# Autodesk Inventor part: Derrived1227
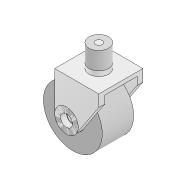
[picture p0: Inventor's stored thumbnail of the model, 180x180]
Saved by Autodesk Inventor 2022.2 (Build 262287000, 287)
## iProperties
Created: 2021-12
Part Number: Derrived1227
Material: 一般
Document SubType Name: Modeling
Designer: taeku
Density: 1 g/cm^3
Appearance: 既定
Author: taeku
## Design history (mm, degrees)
derived "Holder.ipt"
node "作業平面1"
feature "分割1"
  node "ソリッド1"
sketch "スケッチ1"
  geometry: C1 r 12 at (12, -40); C2 r 6 at (12, -40); A1 r 12 centre (12, -40) between (0, -40) and (21.996, -46.639) reference; 3 further points
  constraints: 2 centre point, 2 coincident
extrude "押し出し1" new body sketch "スケッチ1" distance "d2" = 6.5; taper "d3" = 0 deg
mirror "ミラー1"
sketch "スケッチ2"
  geometry: C1 r 6 at (0, 0); C2 r 30 at (0, 0); 1 further point
  constraints: 2 centre point, 2 coincident
  dimensions: "d4" = 60 diameter of C2
extrude "押し出し2" new body sketch "スケッチ2" stored distance "d5" = 32; taper "d6" = 0 deg
sketch "スケッチ3"
  geometry: C1 r 3.5 at (0, 0); C2 r 10 at (0, 0); 1 further point
  constraints: 2 centre point, 1 coincident
extrude "押し出し3" new body sketch "スケッチ3" stored distance "d7" = 33; taper "d8" = 0 deg
feature "ソリッド1::Holder.ipt" dims "d0" = 10
tag "TaggingFeature1"
node "保持2"
feature "次のパターン 保持2:1"
node "保持3"
node "障害物1"
node "障害物2"
node "保持1"
node "元の形状"
other parameters: "d1" = 0
